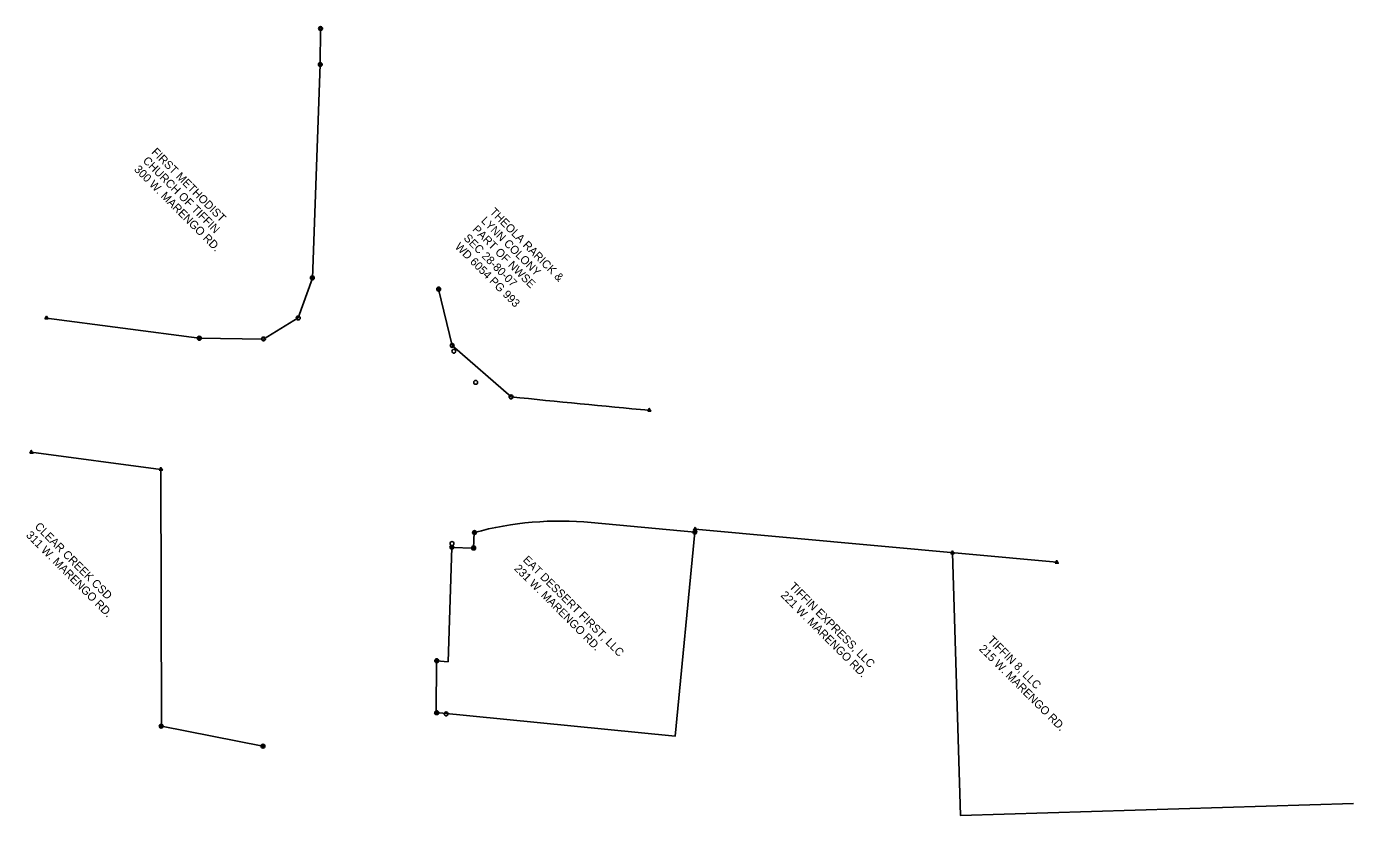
# Model space of a CAD drawing. Extents: x 20499797 to 20500563, y 7952063 to 7954287.
import ezdxf

# ---------------------------------------------------------------- set-up
doc = ezdxf.new("R2010")
doc.units = 0
for name, color, linetype in [('DisROW Existing', 7, 'Continuous'), ('DisROW Property Lines', 7, 'Continuous'), ('SurControl', 7, 'Continuous'), ('Text', 7, 'Continuous'), ('V-SITE-FENC', 7, 'Continuous'), ('V-SITE-STRC', 7, 'Continuous')]:
    doc.layers.add(name, color=color, linetype=linetype)

msp = doc.modelspace()

# ---------------------------------------------------------------- linework, layer by layer
at = {"layer": 'DisROW Existing'}
for p, q in [((20499966.38, 7954265.32), (20499966.49, 7954285.76)), ((20499961.78, 7954141.97), (20499966.38, 7954265.32)), ((20499953.6, 7954118.91), (20499961.78, 7954141.97)), ((20500034.66, 7954135.61), (20500042.48, 7954103.08)), ((20499808.32, 7954118.88), (20499896.55, 7954107.19)), ((20499933.56, 7954106.75), (20499953.6, 7954118.91)), ((20499896.55, 7954107.19), (20499933.56, 7954106.75)), ((20500042.48, 7954103.08), (20500076.49, 7954073.36)), ((20499874.3, 7954031.45), (20499799.58, 7954041.35)), ((20499874.75, 7953883.15), (20499874.3, 7954031.45)), ((20500182.53, 7953995.26), (20500122.78, 7954000.78)), ((20500055.22, 7953994.98), (20500054.83, 7953985.93)), ((20500182.68, 7953996.91), (20500182.53, 7953995.26)), ((20500391.37, 7953977.79), (20500182.68, 7953996.91)), ((20500042.21, 7953986.42), (20500040.08, 7953920.25)), ((20500054.83, 7953985.93), (20500042.21, 7953986.42)), ((20500033.45, 7953920.94), (20500033.28, 7953891.03)), ((20500040.08, 7953920.25), (20500033.45, 7953920.94)), ((20499933.17, 7953871.63), (20499874.75, 7953883.15))]:
    msp.add_line(p, q, dxfattribs=at)
for centre, radius, start, end in [((20500665.28, 7959721.75), 5679, 264.04903, 264.8572), ((20500104.82, 7953813.64), 188, 84.51748, 105.29724)]:
    msp.add_arc(centre, radius, start, end, dxfattribs=at)
at = {"layer": 'DisROW Property Lines'}
for points in [[(20500182.53, 7953995.26), (20500171.1, 7953877.37), (20500033.28, 7953891.03)], [(20500562.63, 7953838.43), (20500335.76, 7953831.59), (20500331.18, 7953983.3)]]:
    msp.add_lwpolyline(points, dxfattribs=at)
at = {"layer": 'SurControl'}
for centre in [(20499966.55, 7954286.1), (20499966.36, 7954265.3), (20499961.79, 7954142.03), (20500034.68, 7954135.6), (20499953.64, 7954118.89), (20499896.54, 7954107.19), (20499933.6, 7954106.79), (20500042.47, 7954103.03), (20500043.42, 7954099.7), (20500056.05, 7954081.71), (20500076.47, 7954073.32), (20500055.35, 7953994.99), (20500182.52, 7953995.26), (20500042.3, 7953986.55), (20500042.38, 7953988.6), (20500054.89, 7953986.05), (20500033.58, 7953920.93), (20500033.52, 7953890.94), (20500038.99, 7953890.26), (20499874.56, 7953883.19), (20499933.29, 7953871.61)]:
    msp.add_circle(centre, 1.12, dxfattribs=at)
at = {"layer": 'V-SITE-FENC'}
for points in [[(20499965.58, 7954285.23), (20499967.41, 7954285.23), (20499966.49, 7954286.81)], [(20499965.46, 7954264.79), (20499967.29, 7954264.79), (20499966.38, 7954266.37)], [(20499960.87, 7954141.5), (20499962.7, 7954141.5), (20499961.79, 7954143.08)], [(20500033.75, 7954135.08), (20500035.58, 7954135.08), (20500034.66, 7954136.67)], [(20499807.4, 7954118.35), (20499809.23, 7954118.35), (20499808.32, 7954119.93)], [(20499895.63, 7954106.66), (20499897.46, 7954106.66), (20499896.55, 7954108.24)], [(20500155.31, 7954065.08), (20500157.13, 7954065.08), (20500156.22, 7954066.67)], [(20499798.67, 7954040.82), (20499800.49, 7954040.82), (20499799.58, 7954042.41)], [(20499873.38, 7954030.92), (20499875.21, 7954030.92), (20499874.3, 7954032.5)], [(20500054.3, 7953994.45), (20500056.13, 7953994.45), (20500055.22, 7953996.03)], [(20500181.61, 7953994.73), (20500183.44, 7953994.73), (20500182.53, 7953996.31)], [(20500181.76, 7953996.38), (20500183.59, 7953996.38), (20500182.68, 7953997.96)], [(20500041.29, 7953985.89), (20500043.12, 7953985.89), (20500042.21, 7953987.47)], [(20500053.91, 7953985.4), (20500055.74, 7953985.4), (20500054.83, 7953986.98)], [(20500330.26, 7953982.77), (20500332.09, 7953982.77), (20500331.18, 7953984.36)], [(20500390.46, 7953977.26), (20500392.29, 7953977.26), (20500391.37, 7953978.84)], [(20500032.54, 7953920.41), (20500034.36, 7953920.41), (20500033.45, 7953922)], [(20500032.36, 7953890.5), (20500034.19, 7953890.5), (20500033.28, 7953892.08)], [(20499873.64, 7953882.66), (20499875.47, 7953882.66), (20499874.56, 7953884.24)], [(20499932.37, 7953871.08), (20499934.2, 7953871.08), (20499933.29, 7953872.66)]]:
    msp.add_lwpolyline(points, close=True, dxfattribs=at)
at = {"layer": 'V-SITE-STRC'}
for points in [[(20499966.49, 7954285.76), (20499966.49, 7954285.76)], [(20499966.38, 7954265.32), (20499966.38, 7954265.32)], [(20499961.79, 7954142.02), (20499961.79, 7954142.03)], [(20500034.66, 7954135.61), (20500034.66, 7954135.61)], [(20499808.32, 7954118.88), (20499808.32, 7954118.88)], [(20499953.6, 7954118.91), (20499953.6, 7954118.91)], [(20499896.55, 7954107.19), (20499896.55, 7954107.19)], [(20499933.56, 7954106.75), (20499933.56, 7954106.75)], [(20500042.48, 7954103.08), (20500042.48, 7954103.08)], [(20500076.47, 7954073.32), (20500076.47, 7954073.32)], [(20500156.22, 7954065.61), (20500156.22, 7954065.61)], [(20499799.58, 7954041.35), (20499799.58, 7954041.35)], [(20499874.3, 7954031.45), (20499874.3, 7954031.45)], [(20500055.22, 7953994.97), (20500055.22, 7953994.98)], [(20500182.53, 7953995.26), (20500182.53, 7953995.26)], [(20500182.68, 7953996.91), (20500182.68, 7953996.91)], [(20500042.21, 7953986.41), (20500042.21, 7953986.42)], [(20500054.83, 7953985.93), (20500054.83, 7953985.93)], [(20500331.18, 7953983.3), (20500331.18, 7953983.3)], [(20500391.37, 7953977.79), (20500391.37, 7953977.79)], [(20500033.45, 7953920.94), (20500033.45, 7953920.94)], [(20500033.28, 7953891.03), (20500033.28, 7953891.03)], [(20499874.56, 7953883.19), (20499874.56, 7953883.19)], [(20499933.29, 7953871.61), (20499933.29, 7953871.61)]]:
    msp.add_lwpolyline(points, dxfattribs=at)

# ---------------------------------------------------------------- texts
at = {"layer": 'Text'}
for s, p in [('FIRST METHODIST', (20499868.62, 7954214.35)), ('300 W. MARENGO RD.', (20499858.6, 7954204.33)), ('CHURCH OF TIFFIN', (20499863.61, 7954209.34)), ('LYNN COLONY', (20500058.8, 7954174.7)), ('THEOLA RARICK &', (20500063.81, 7954179.71)), ('PART OF NWSE', (20500053.79, 7954169.69)), ('WD 6054 PG 993', (20500043.76, 7954159.67)), ('SEC 28-80-07', (20500048.77, 7954164.68)), ('CLEAR CREEK CSD', (20499801.22, 7953998.09)), ('311 W. MARENGO RD.', (20499796.21, 7953993.09)), ('EAT DESSERT FIRST, LLC', (20500082.96, 7953978.81)), ('231 W. MARENGO RD.', (20500077.95, 7953973.8)), ('TIFFIN EXPRESS, LLC', (20500236.71, 7953963.41)), ('221 W. MARENGO RD.', (20500231.7, 7953958.4)), ('TIFFIN 8, LLC', (20500351.22, 7953932.45)), ('215 W. MARENGO RD.', (20500346.21, 7953927.44))]:
    msp.add_text(s, height=4.7244, rotation=314.98356, dxfattribs=at).set_placement(p)

doc.saveas('drawing.dxf')
